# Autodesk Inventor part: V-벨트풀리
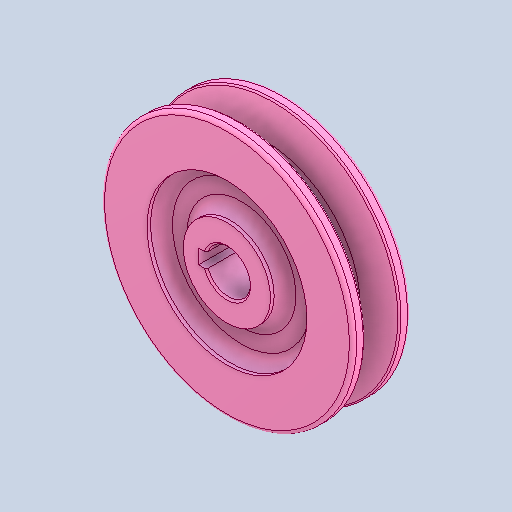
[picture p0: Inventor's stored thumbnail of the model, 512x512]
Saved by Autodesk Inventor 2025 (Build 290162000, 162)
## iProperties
Created: 2025-08
Part Number: V-벨트풀리
Material: 강철, 연강
Document SubType Name: Modeling
Designer: infra02
Density: 7.86 g/cm^3
Appearance: 기본값
Author: jhkim
Sending System: Autodesk Inventor 2026
Preprocessor: ST-DEVELOPER v20.1
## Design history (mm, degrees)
feature "Solid1"
node "솔리드1"
